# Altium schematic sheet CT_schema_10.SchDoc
size 389 x 385 mm
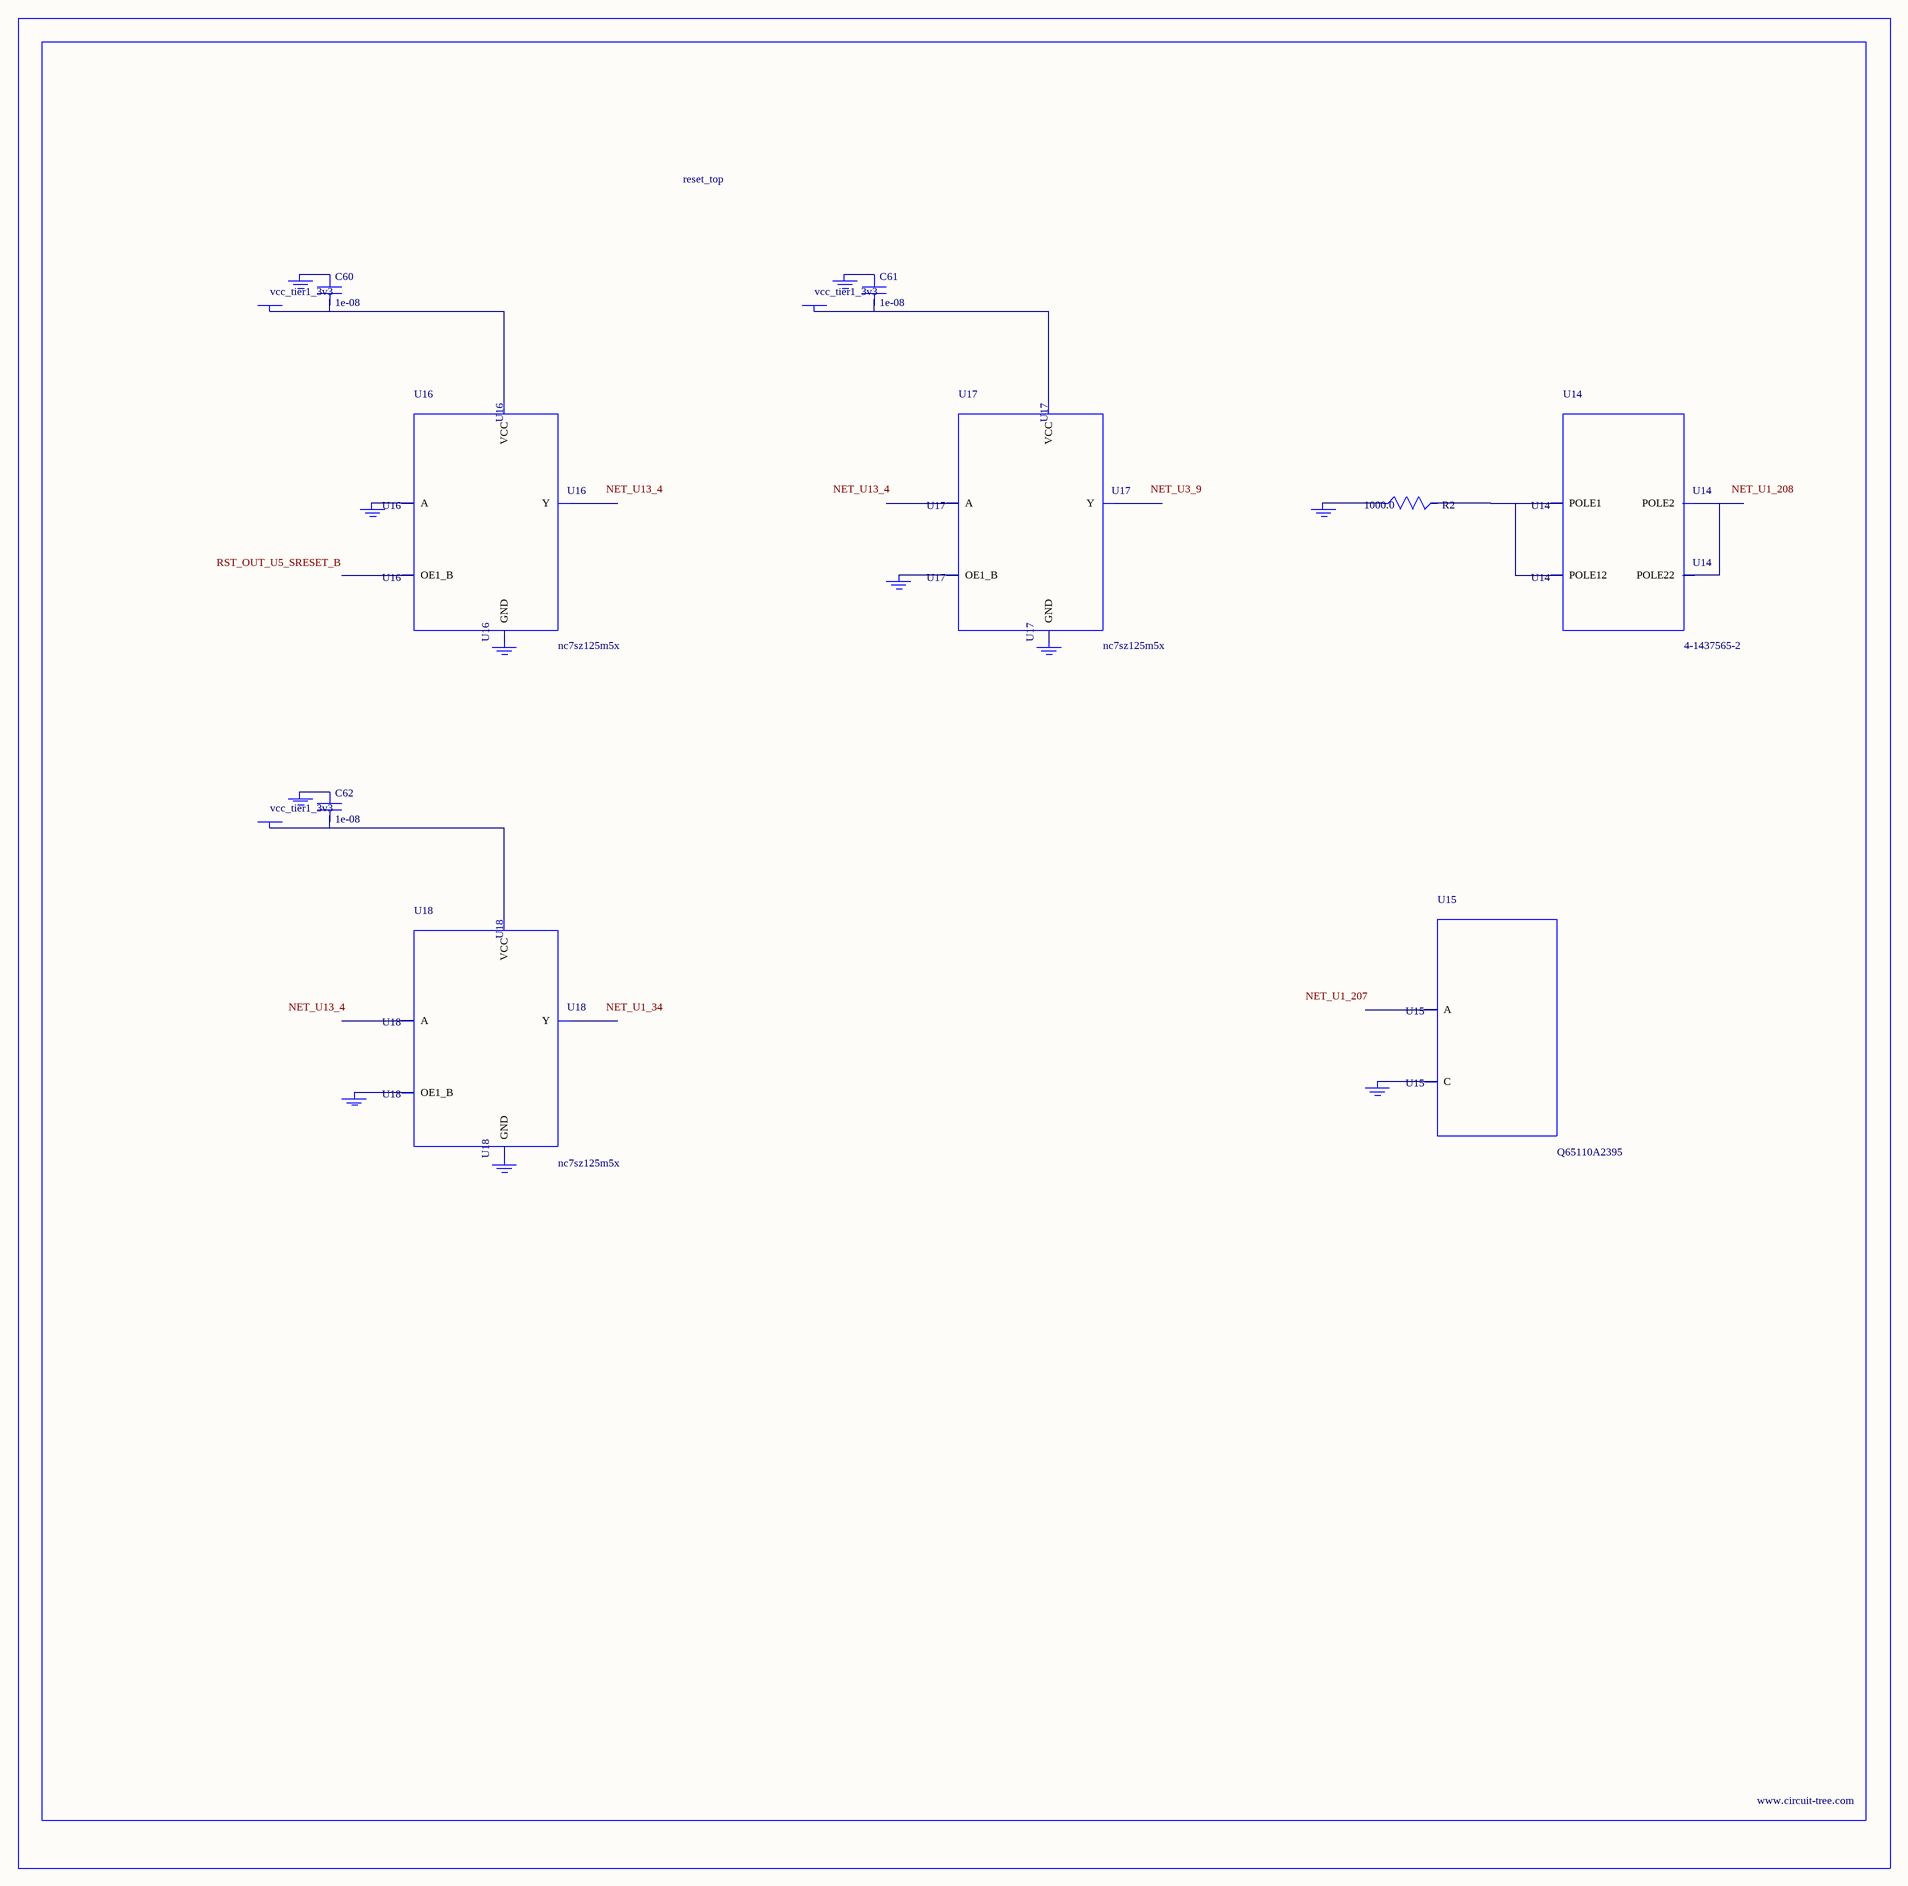
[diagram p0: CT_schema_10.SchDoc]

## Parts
BORDER9  (no value)
C60  1e-08  [C0402]
C61  1e-08  [C0402]
C62  1e-08  [C0402]
GND_INSTANCE_9_0  (no value)
GND_INSTANCE_9_1  (no value)
GND_INSTANCE_9_2  (no value)
GND_INSTANCE_9_3  (no value)
GND_INSTANCE_9_4  (no value)
GND_INSTANCE_9_5  (no value)
GND_INSTANCE_9_6  (no value)
GND_INSTANCE_9_7  (no value)
GND_INSTANCE_9_8  (no value)
GND_INSTANCE_9_9  (no value)
GND_INSTANCE_9_10  (no value)
POWER_INSTANCE_9_0  vcc_tier1_3v3
POWER_INSTANCE_9_1  vcc_tier1_3v3
POWER_INSTANCE_9_2  vcc_tier1_3v3
R2  1000.0  [R0603]
U14  4-1437565-2  [SW_4-1437565-2]
U15  Q65110A2395  [LGM67K-G1J2-24-Z]
U16  nc7sz125m5x  [NC7SZ125M5X]
U17  nc7sz125m5x  [NC7SZ125M5X]
U18  nc7sz125m5x  [NC7SZ125M5X]

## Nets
NetC60_1: C60.1 GND_INSTANCE_9_2.0(GND)
NetC60_2: C60.2 POWER_INSTANCE_9_0.0(PWR) U16.5(VCC)
NetC61_1: C61.1 GND_INSTANCE_9_5.0(GND)
NetC61_2: C61.2 POWER_INSTANCE_9_1.0(PWR) U17.5(VCC)
NetC62_1: C62.1 GND_INSTANCE_9_8.0(GND)
NetC62_2: C62.2 POWER_INSTANCE_9_2.0(PWR) U18.5(VCC)
NetGND_INSTANCE_9_0_0: GND_INSTANCE_9_0.0(GND) R2.1
NetGND_INSTANCE_9_1_0: GND_INSTANCE_9_1.0(GND) U15.C
NetGND_INSTANCE_9_3_0: GND_INSTANCE_9_3.0(GND) U16.2(A)
NetGND_INSTANCE_9_4_0: GND_INSTANCE_9_4.0(GND) U16.3(GND)
NetGND_INSTANCE_9_6_0: GND_INSTANCE_9_6.0(GND) U17.1(OE1_B)
NetGND_INSTANCE_9_7_0: GND_INSTANCE_9_7.0(GND) U17.3(GND)
NetGND_INSTANCE_9_9_0: GND_INSTANCE_9_9.0(GND) U18.1(OE1_B)
NetGND_INSTANCE_9_10_0: GND_INSTANCE_9_10.0(GND) U18.3(GND)
NetR2_2: R2.2 U14.1(POLE1) U14.2(POLE12)
NetU14_3: U14.3(POLE2) U14.4(POLE22)

Not connected (* = marked no-connect by the designer): U15 A; U16 1(OE1_B) 4(Y); U17 2(A) 4(Y); U18 2(A) 4(Y)

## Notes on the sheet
- Labels drawn without touching a wire or pin: NET_U1_34, NET_U1_207, NET_U1_208, NET_U3_9, NET_U13_4, RST_OUT_U5_SRESET_B

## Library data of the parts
BORDER9 = BORDER_PAGE9
C60-C62 = C0402C103K3RAC
GND_INSTANCE_9_0-GND_INSTANCE_9_10 = GND
POWER_INSTANCE_9_0-POWER_INSTANCE_9_2 = PWR
R2 = RC0603JR-071KL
